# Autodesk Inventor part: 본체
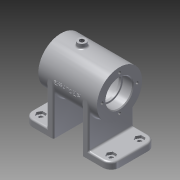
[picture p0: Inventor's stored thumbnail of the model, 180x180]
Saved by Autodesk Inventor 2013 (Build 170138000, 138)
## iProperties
Created: 2017-02
Part Number: 본체
Material: 알루미늄 6061
Document SubType Name: Modeling
Designer: Administrator
Density: 2.71 g/cm^3
Mass: 356.066 g
Surface Area: 422.768 cm^2
Volume: 131.39 cm^3
Author: Administrator
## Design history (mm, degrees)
sketch "스케치2"
  geometry: C1 r 27 at (0, 0); 1 further point
  constraints: 1 centre point, 1 coincident
  dimensions: "d0" = 54 diameter of C1
extrude "돌출1" new body sketch "스케치2" stored distance "d1" = 70; taper "d2" = 0 deg
hole "구멍1" diameter "d5" = 28; stored, may be unused: countersink angle "d9" = 90 deg, drill point angle "d11" = 118 deg; dims "d3" = 10, "d4" = 10, "d6" = 6, "d7" = 32, "d8" = 12, "d10" = 8
hole "구멍2" diameter "d14" = 28; stored, may be unused: countersink angle "d18" = 90 deg, drill point angle "d20" = 118 deg; dims "d12" = 10, "d13" = 10, "d15" = 6, "d16" = 32, "d17" = 12, "d19" = 8
sketch "스케치3"
  geometry: C1 r 22 at (0, 0); 1 further point
  constraints: 1 centre point, 1 coincident
  dimensions: "d21" = 44 diameter of C1
extrude "돌출2" cut sketch "스케치3" stored distance "d22" = 40; taper "d23" = 0 deg
sketch "스케치4" dims "d24" = 42
  geometry: C1 r 27 at (0, 0) reference; 3 further points
  constraints: 2 vertical alignment, 1 coincident, 2 other
hole "구멍3" sketch "스케치4" at (0, 21) diameter "d25" = 3.242; stored, may be unused: countersink angle "d29" = 90 deg, drill point angle "d31" = 118 deg; dims "d26" = 8, "d27" = 32, "d28" = 12, "d30" = 10
fillet "모깎기1" dims "d35" = 0.3
fillet "모깎기2" dims "d36" = 3
node "작업 평면1"
sketch "스케치6"
  geometry: L1 (-52, 27)-(-17, 27); L2 (-17, -27)-(-52, -27); L3 (-52, -27)-(-52, 27); L4 (-17, -27)-(-17, -22.125); L5 (-17, -22.125)-(-17, 27); L6 (-52, 0)-(0, 0)
  constraints: 12 end point, 3 perpendicular, 1 horizontal, 1 midpoint, 1 parallel
  dimensions: "d41" = 17 distance from line of L5 L6.end; "d42" = 54 distance of L2.end L1.start; "d43" = 35 distance of L1.start L1.end; "d44" = 52 distance from line of L6.end L3
extrude "돌출3" join sketch "스케치6" distance "d45" = 8; taper "d46" = 0 deg
sketch "스케치7"
  geometry: L1 (-17, 27)-(-17, -27) reference; L2 (-17, 27)-(-25, 27); L3 (-25, 27)-(-25, -27); L4 (-25, -27)-(-17, -27); L5 (-17, -27)-(-17, 27); 1 further point
  constraints: 8 end point, 2 parallel, 1 horizontal, 1 perpendicular
  dimensions: "d47" = 8 distance of L1.start L2.end
extrude "돌출4" join sketch "스케치7" stored distance "d48" = 8; taper "d49" = 0 deg
fillet "모깎기3" dims "d50" = 10
sketch "스케치8"
  geometry: 2 further points
  dimensions: "d51" = 17 vertical distance of point (-42, 17) point (0, 0); "d52" = 42 horizontal distance of point (-42, 17) point (0, 0)
hole "구멍4" sketch "스케치8" at (-42, 17) diameter "d53" = 5; stored, may be unused: countersink angle "d57" = 90 deg, drill point angle "d59" = 118 deg; dims "d54" = 8, "d55" = 32, "d56" = 12, "d58" = 10
sketch "스케치9"
  geometry: L1 (-36.804, 17)-(-39.402, 12.5); L2 (-39.402, 12.5)-(-44.598, 12.5); L3 (-44.598, 12.5)-(-47.196, 17); L4 (-47.196, 17)-(-44.598, 21.5); L5 (-44.598, 21.5)-(-39.402, 21.5); L6 (-39.402, 21.5)-(-36.804, 17); C1 r 2.5 at (-42, 17) reference; C2 r 4.5 at (-42, 17); 2 further points
  constraints: 12 end point, 2 coincident, 1 centre point, 1 horizontal, 13 other
  dimensions: "d60" = 9 distance between parallel lines of L2 L5; "d61" = 9 diameter of C2
extrude "돌출5" cut sketch "스케치9" distance "d62" = 3; taper "d63" = 0 deg
node "작업 평면2"
sketch "스케치10"
  geometry: L1 (-35, 27)-(-35, -27) reference; C1 r 5 at (-10, 0); 1 further point
  constraints: 1 centre point, 1 horizontal alignment
  dimensions: "d108" = 10 diameter of C1; "d109" = 25 distance from line of L1 C1.centre
extrude "돌출6" join sketch "스케치10" stored distance "d66" = 3; taper "d67" = 0 deg
sketch "스케치11"
  geometry: L1 (0, 0)-(0, -27); L2 (0, 0)-(16.339, -25.16); A1 r 27 centre (0, 0) between (-27, 0) and (27, 0) reference; 1 further point
  constraints: 4 end point, 1 coincident, 1 point on circle, 1 vertical
  dimensions: "d77" = 30 distance of L1.start L2.end; "d79" = 33 deg angle of L2 L1
node "작업 평면3"
sketch "스케치12"
  geometry: C1 r 6 at (0, 0); 1 further point
  constraints: 1 centre point, 1 coincident
  dimensions: "d82" = 12 diameter of C1
extrude "돌출7" join sketch "스케치12" stored distance "d83" = 3; taper "d84" = 0 deg
hole "구멍6" diameter "d87" = 5.188; stored, may be unused: countersink angle "d91" = 90 deg, drill point angle "d93" = 118 deg; dims "d85" = 10, "d86" = 10, "d88" = 8, "d89" = 32, "d90" = 12, "d92" = 10
chamfer "모따기1" distance "d94" = 1; stored, may be unused: second distance "d95" = 2, angle "d96" = 45 deg
chamfer "모따기2" distance "d97" = 1; stored, may be unused: second distance "d98" = 2, angle "d99" = 45 deg
fillet "모깎기4" dims "d100" = 2
fillet "모깎기5" dims "d101" = 2
fillet "모깎기6" dims "d102" = 2
node "작업 평면4"
sketch "스케치13"
  geometry: L1 (-29.895, 2.402)-(29.895, 2.402); L2 (29.895, 2.402)-(29.895, -2.402); L3 (29.895, -2.402)-(-29.895, -2.402); L4 (-29.895, -2.402)-(-29.895, 2.402); L5 (-29.895, 0)-(29.895, 0); L6 (0, 2.402)-(0, -2.402); L7 (-35, 27)-(35, 27) reference; L8 (-35, 27)-(-35, -27) reference; 1 further point
  constraints: 4 end point, 4 midpoint, 2 other
  dimensions: "d104" = 27 distance between parallel lines of L7 L5; "d105" = 35 distance between parallel lines of L6 L8
feature "엠보싱1" sketch "스케치13" dims "d0" = 54, "d24" = 42, "d106" = 0.5, "d107" = 0
hole "구멍7" diameter "d112" = 5.188; stored, may be unused: countersink angle "d116" = 90 deg, drill point angle "d118" = 118 deg; dims "d110" = 10, "d111" = 10, "d113" = 8, "d114" = 32, "d115" = 12, "d117" = 10
fillet "모깎기7" dims "d119" = 2
node "솔리드1"
pattern_circular "원형 패턴1" dims angle "d33" = 360 deg
mirror "대칭1"
mirror "대칭2"
mirror "대칭3"
other parameters: "d64" = 92, "d103" = -41.25
